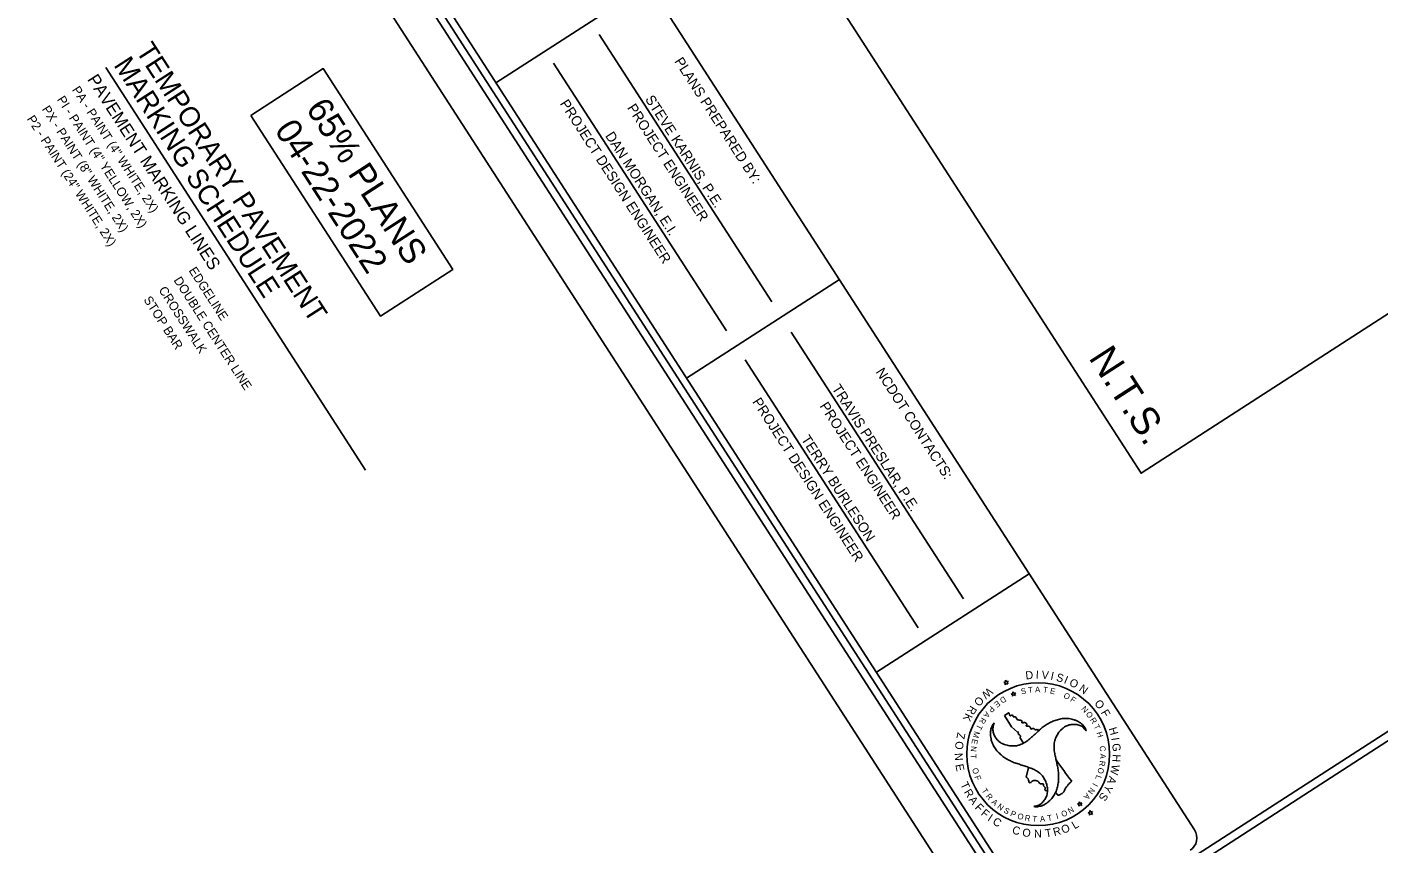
# Model space of a CAD drawing. Extents: x 2160312 to 2162215, y 789569 to 792090.
# Drawn here: x 2160312 to 2161255, y 790620 to 791189 of the extents above; entities that cross this region are included whole.
import ezdxf

# ---------------------------------------------------------------- set-up
doc = ezdxf.new("R2010")
doc.units = 0
for name, color, linetype in [('Default', 7, 'Continuous'), ('DEV BORDER CELL', 7, 'Continuous'), ('DEV TITLE SHEET CELL', 7, 'Continuous'), ('Gray Area Fill Shapes', 7, 'Continuous'), ('Old_Level_4', 7, 'Continuous'), ('Scratch_Level_4', 7, 'Continuous'), ('Sheet Plot Border Outside CELL', 7, 'Continuous'), ('Sheet Sticker Incomplete CELL', 7, 'Continuous')]:
    doc.layers.add(name, color=color, linetype=linetype)

msp = doc.modelspace()

# ---------------------------------------------------------------- linework, layer by layer
at = {"layer": 'DEV BORDER CELL'}
msp.add_line((2160547.96, 790880.49), (2160366.85, 791161.07), dxfattribs=at)
at = {"layer": 'DEV TITLE SHEET CELL'}
for p, q in [((2160611.25, 791427.06), (2161126.03, 790629.59)), ((2160490.55, 791361.48), (2161292.92, 790118.52)), ((2160497.63, 791360.29), (2161018.15, 790553.95)), ((2161019.55, 790560.85), (2160504.76, 791358.31)), ((2160745.54, 791219.17), (2160638.96, 791150.48)), ((2160710.9, 791184.09), (2160831.22, 790997.65)), ((2160679.13, 791164.22), (2160799.67, 790977.47)), ((2161888.56, 791103.58), (2161032.36, 790550.88)), ((2161891.61, 791098.86), (2161035.42, 790546.16)), ((2160844.75, 790976.71), (2160964.84, 790790.65)), ((2160812.73, 790957.28), (2160933.26, 790770.5)), ((2161010.85, 790808.18), (2160904.27, 790739.48)), ((2160994.16, 790732.73), (2160992.99, 790732.4)), ((2160992.99, 790732.4), (2160994.1, 790732)), ((2160994.1, 790732), (2160994.03, 790730.79)), ((2160994.1, 790732), (2160994.03, 790730.8)), ((2160994.03, 790730.79), (2160994.81, 790731.72)), ((2160994.03, 790730.8), (2160994.81, 790731.72)), ((2160994.23, 790733.94), (2160994.16, 790732.73)), ((2160994.88, 790732.93), (2160994.23, 790733.94)), ((2160994.81, 790731.72), (2160995.94, 790731.28)), ((2160994.81, 790731.72), (2160995.94, 790731.29)), ((2160996, 790733.23), (2160994.88, 790732.93)), ((2160995.29, 790732.29), (2160996, 790733.23)), ((2160995.94, 790731.29), (2160995.29, 790732.29)), ((2160999.36, 790724.64), (2160998.2, 790724.31)), ((2160998.2, 790724.31), (2160999.3, 790723.92)), ((2160999.3, 790723.92), (2160999.23, 790722.71)), ((2160999.23, 790722.71), (2161000.01, 790723.63)), ((2160999.43, 790725.85), (2160999.36, 790724.64)), ((2161000.08, 790724.84), (2160999.43, 790725.85)), ((2161000.01, 790723.63), (2161001.14, 790723.2)), ((2161001.21, 790725.15), (2161000.08, 790724.84)), ((2161000.49, 790724.21), (2161001.21, 790725.15)), ((2161001.14, 790723.2), (2161000.49, 790724.21)), ((2160993.65, 790709.4), (2160996.18, 790710.92)), ((2160998.41, 790701.4), (2160993.65, 790709.4)), ((2161002.61, 790697.78), (2160998.41, 790701.4)), ((2161004.31, 790693.99), (2161006.81, 790690.05)), ((2161010.35, 790673.16), (2161008.59, 790666.34)), ((2161045.58, 790647.96), (2161044.42, 790647.63)), ((2161044.42, 790647.63), (2161045.52, 790647.23)), ((2161045.52, 790647.23), (2161045.46, 790646.02)), ((2161045.46, 790646.02), (2161046.23, 790646.95)), ((2161045.65, 790649.16), (2161045.58, 790647.96)), ((2161046.3, 790648.15), (2161045.65, 790649.16)), ((2161046.23, 790646.95), (2161047.36, 790646.51)), ((2161047.43, 790648.46), (2161046.3, 790648.15)), ((2161046.71, 790647.52), (2161047.43, 790648.46)), ((2161047.36, 790646.51), (2161046.71, 790647.52)), ((2161053.02, 790641.84), (2161051.85, 790641.51)), ((2161053.08, 790643.05), (2161053.02, 790641.84)), ((2161053.74, 790642.04), (2161053.08, 790643.05)), ((2161054.86, 790642.34), (2161053.74, 790642.04)), ((2161054.15, 790641.4), (2161054.86, 790642.34)), ((2161051.85, 790641.51), (2161052.96, 790641.11)), ((2161052.96, 790641.11), (2161052.89, 790639.9)), ((2161052.89, 790639.9), (2161053.67, 790640.83)), ((2161053.67, 790640.83), (2161054.8, 790640.39)), ((2161054.8, 790640.39), (2161054.15, 790641.4))]:
    msp.add_line(p, q, dxfattribs=at)
msp.add_circle((2161017.03, 790682.35), 49.83, dxfattribs=at)
for centre, radius, start, end in [((2161243.56, 790823.19), 258.4, 208.52183, 208.81957), ((2161243.56, 790823.19), 258.4, 214.04685, 218.1669), ((2161117.38, 790624.01), 10.29, 302.84337, 32.84337)]:
    msp.add_arc(centre, radius, start, end, dxfattribs=at)
for points in [[(2160996.18, 790710.92), (2160996.36, 790711.15), (2160996.9, 790710.89), (2160997.17, 790709.43), (2160998.04, 790709.18), (2160998.53, 790709.53), (2160999.33, 790709.37), (2160999.68, 790708.48), (2161001.04, 790708.35), (2161001.65, 790707.81), (2161002.55, 790706.42), (2161005.27, 790705.83), (2161005.82, 790705.21), (2161005.49, 790704.74), (2161005.68, 790704.27), (2161007.53, 790704.42), (2161007.83, 790704.35), (2161009.17, 790703.43), (2161009.13, 790702.92), (2161008.59, 790702.42), (2161008.61, 790702.17), (2161009.17, 790701.94), (2161010.28, 790701.83), (2161011.51, 790701.14), (2161012.13, 790699.82), (2161013.27, 790700.26), (2161015.13, 790699.45), (2161015.9, 790699.53), (2161016.53, 790699.83)], [(2161013.94, 790645.94), (2161016.75, 790646.62), (2161019.26, 790648.06), (2161021.16, 790650.21), (2161022.73, 790652.88), (2161023.52, 790656.05), (2161023.55, 790658.41), (2161023.28, 790659.55), (2161022.96, 790661.46), (2161022.37, 790663.03), (2161020.89, 790665.82), (2161018.78, 790668.54), (2161015.89, 790670.67), (2161015.64, 790670.83), (2161012.67, 790672.31), (2161009.48, 790673.47), (2161006.37, 790674.55), (2161003.12, 790675.52), (2160999.89, 790676.59), (2160996.98, 790678.01), (2160993.75, 790679.89), (2160991.2, 790681.82), (2160988.77, 790684.21), (2160987.62, 790685.45), (2160986.88, 790686.71), (2160985.14, 790689.73), (2160984.16, 790693.1), (2160983.81, 790695.14), (2160983.81, 790696.94), (2160983.79, 790697.25), (2160984.34, 790700.51), (2160985.65, 790703.3), (2160986.35, 790704.14)], [(2160986.35, 790704.14), (2160985.52, 790701.31), (2160985.53, 790698.44), (2160986.43, 790695.73), (2160987.97, 790693.01), (2160990.33, 790690.74), (2160992.37, 790689.54), (2160993.45, 790689.18), (2160995.32, 790688.55), (2160996.91, 790688.27), (2161000.11, 790688.14), (2161003.49, 790688.61), (2161006.78, 790690.03), (2161007.05, 790690.17), (2161009.83, 790692), (2161012.42, 790694.2), (2161014.88, 790696.36), (2161017.38, 790698.68), (2161019.89, 790700.94), (2161022.58, 790702.75), (2161025.82, 790704.59), (2161028.78, 790705.86), (2161032.1, 790706.76), (2161033.7, 790707.13), (2161035.17, 790707.16), (2161038.69, 790707.13), (2161042.06, 790706.29), (2161044.02, 790705.57), (2161045.57, 790704.7), (2161045.84, 790704.56), (2161048.4, 790702.46), (2161050.18, 790699.92), (2161050.52, 790698.9)], [(2161050.64, 790698.88), (2161050.52, 790698.9), (2161048.52, 790701.01), (2161046, 790702.46), (2161043.21, 790703.04), (2161040.12, 790703.06), (2161036.96, 790702.15), (2161034.9, 790701), (2161034.06, 790700.21), (2161032.56, 790698.92), (2161031.5, 790697.71), (2161029.84, 790694.96), (2161028.53, 790691.83), (2161028.13, 790688.23), (2161028.11, 790687.94), (2161028.28, 790684.65), (2161028.91, 790681.26), (2161029.55, 790678.07), (2161030.31, 790674.77), (2161030.96, 790671.45), (2161031.21, 790668.21), (2161031.21, 790664.48), (2161030.82, 790661.3), (2161029.96, 790657.98), (2161029.46, 790656.38), (2161028.74, 790655.1), (2161026.98, 790652.05), (2161024.55, 790649.57), (2161022.95, 790648.21), (2161021.42, 790647.29), (2161021.17, 790647.13), (2161018.04, 790646), (2161014.95, 790645.74), (2161013.94, 790645.94)], [(2161004.31, 790693.99), (2161004.71, 790694.7), (2161004.48, 790695.45), (2161003.48, 790696.03), (2161003.09, 790696.67), (2161003.16, 790697.72), (2161002.61, 790697.78)], [(2161008.59, 790666.34), (2161010.08, 790665.07), (2161010.43, 790663.43), (2161010.73, 790662.73), (2161011.47, 790662.46), (2161013.34, 790663.89), (2161014.55, 790664.04), (2161017.5, 790662.93), (2161018.64, 790661.8), (2161020.48, 790661.61), (2161020.71, 790661.2), (2161020.75, 790660.37), (2161021.89, 790659.2), (2161021.71, 790657.56), (2161022.17, 790656.96), (2161023.49, 790657.1)], [(2161029.21, 790655.89), (2161030.98, 790653.77), (2161033.01, 790654.61), (2161034.55, 790655.57), (2161035.7, 790657.65), (2161038.02, 790661.16), (2161040.41, 790663.52)]]:
    msp.add_spline(points, degree=3, dxfattribs=at)
at = {"layer": 'Gray Area Fill Shapes'}
msp.add_line((2160878.45, 791013.22), (2160771.87, 790944.53), dxfattribs=at)
at = {"layer": 'Scratch_Level_4'}
msp.add_lwpolyline([(2161273.01, 791582.16), (2161539.58, 791169.21), (2161088.81, 790878.23), (2160822.24, 791291.18)], close=True, dxfattribs=at)
at = {"layer": 'Sheet Plot Border Outside CELL'}
msp.add_lwpolyline([(2160375.57, 791493.51), (2161291.05, 790075.32), (2162215.22, 790671.9), (2161299.74, 792090.09)], close=True, dxfattribs=at)
at = {"layer": 'Sheet Sticker Incomplete CELL'}
msp.add_lwpolyline([(2160468.04, 791127.78), (2160518.5, 791160.35), (2160608.84, 791020.4), (2160558.38, 790987.82)], close=True, dxfattribs=at)

# ---------------------------------------------------------------- texts
at = {"layer": 'Default'}
for s, height, p in [('PAVEMENT MARKING LINES', 8.75, (2160353.68, 791152.87)), ('PI - PAINT (4" YELLOW, 2X)', 6.25, (2160332.62, 791138.84)), ('PA - PAINT (4" WHITE, 2X)', 6.25, (2160343.12, 791145.62)), ('PX - PAINT (8" WHITE, 2X)', 6.25, (2160322.11, 791132.06)), ('P2 - PAINT (24" WHITE, 2X)', 6.25, (2160311.61, 791125.28)), ('EDGELINE', 6.25, (2160424.47, 791019.6)), ('DOUBLE CENTER LINE', 6.25, (2160413.97, 791012.82)), ('STOP BAR', 6.25, (2160392.96, 790999.26)), ('CROSSWALK', 6.25, (2160403.47, 791006.04))]:
    msp.add_text(s, height=height, rotation=302.84334, dxfattribs=at).set_placement(p)
at = {"layer": 'DEV BORDER CELL'}
for s, p in [('TEMPORARY PAVEMENT', (2160387.46, 791172.79)), ('MARKING SCHEDULE', (2160372.03, 791162.84))]:
    msp.add_text(s, height=13.9991, rotation=302.80314, dxfattribs=at).set_placement(p)
at = {"layer": 'DEV TITLE SHEET CELL'}
for s, height, rotation, p in [('PLANS PREPARED BY:', 7, 302.80314, (2160763.07, 791165.45)), ('STEVE KARNIS, P.E.', 7, 302.84334, (2160742.7, 791139.02)), ('PROJECT DESIGN ENGINEER', 7, 302.80314, (2160683.26, 791136)), ('PROJECT ENGINEER', 7, 302.80314, (2160730.17, 791133.03)), ('DAN MORGAN, E.I.', 7, 302.84334, (2160714.86, 791113.56)), ('NCDOT CONTACTS:', 7, 302.80314, (2160903.37, 790948.88)), ('TRAVIS PRESLAR, P.E.', 7, 302.84334, (2160872.88, 790937.36)), ('PROJECT DESIGN ENGINEER', 7, 302.80314, (2160817.47, 790928.1)), ('PROJECT ENGINEER', 7, 302.80314, (2160864.37, 790925.13)), ('TERRY BURLESON', 7, 302.84334, (2160851.42, 790902)), ('D', 5.58, 6.30238, (2161008.45, 790734.42)), ('I', 5.58, 358.71127, (2161015.32, 790735.09)), ('V', 5.58, 354.42394, (2161019.22, 790735.06)), ('I', 5.58, 347.71552, (2161025.29, 790734.44)), ('S', 5.58, 343.42818, (2161029.11, 790733.67)), ('I', 5.58, 337.22415, (2161034.52, 790732.06)), ('W', 5.58, 220.99332, (2160982.35, 790729.19)), ('S', 4.02, 12.803, (2161005.43, 790723.94)), ('T', 4.02, 7.72492, (2161010.24, 790724.95)), ('A', 4.02, 2.64683, (2161014.93, 790725.43)), ('T', 4.02, 352.49067, (2161020.18, 790725.44)), ('E', 4.02, 347.41258, (2161024.98, 790724.77)), ('O', 5.58, 332.93682, (2161038.14, 790730.61)), ('N', 5.58, 324.4294, (2161044.95, 790726.95)), ('O', 5.58, 229.95805, (2160975.47, 790723.21)), ('E', 4.02, 218.19343, (2160988.59, 790719.96)), ('D', 4.02, 213.11534, (2160993.04, 790723)), ('O', 4.02, 332.17833, (2161034.25, 790722.03)), ('F', 4.02, 327.10024, (2161038.97, 790719.52)), ('O', 5.58, 308.60829, (2161055.88, 790717.65)), ('K', 5.58, 244.63518, (2160966.48, 790711.35)), ('R', 5.58, 238.3974, (2160969.93, 790716.67)), ('R', 4.02, 238.50577, (2160977.64, 790708.31)), ('A', 4.02, 233.42768, (2160980.67, 790712.48)), ('P', 4.02, 228.3496, (2160984.1, 790716.27)), ('N', 4.02, 311.86599, (2161046.81, 790713.74)), ('O', 4.02, 306.7879, (2161049.97, 790710.31)), ('R', 4.02, 301.70982, (2161052.92, 790706.31)), ('F', 5.58, 300.10087, (2161060.58, 790711.51)), ('T', 4.02, 243.58385, (2160974.91, 790703.54)), ('T', 4.02, 296.63173, (2161055.49, 790701.87)), ('H', 5.58, 286.29732, (2161066.12, 790700.27)), ('O', 5.58, 265.36662, (2160959.48, 790691.58)), ('Z', 5.58, 259.01209, (2160960.86, 790697.89)), ('E', 4.02, 258.81811, (2160971.13, 790693.24)), ('M', 4.02, 253.74002, (2160972.67, 790698.65)), ('H', 4.02, 286.47557, (2161057.57, 790697.35)), ('I', 5.58, 278.64737, (2161067.98, 790693.57)), ('G', 5.58, 274.36004, (2161068.63, 790689.73)), ('N', 5.58, 273.80597, (2160958.75, 790683.03)), ('N', 4.02, 263.89619, (2160970.24, 790688.16)), ('T', 4.02, 274.05236, (2160969.77, 790682.26)), ('C', 4.02, 276.3194, (2161059.8, 790687.93)), ('A', 4.02, 266.16323, (2161060.28, 790682.83)), ('H', 5.58, 266.30657, (2161069.07, 790682.42)), ('E', 5.58, 281.795, (2160959.22, 790674.93)), ('O', 4.02, 284.20853, (2160970.97, 790672.2)), ('O', 4.02, 256.00706, (2161059.22, 790673.31)), ('R', 4.02, 261.08514, (2161060.01, 790678.05)), ('W', 5.58, 258.65662, (2161068.53, 790675.48)), ('T', 5.58, 295.53813, (2160962.64, 790661.41)), ('F', 4.02, 289.28661, (2160972.55, 790666.73)), ('I', 4.02, 240.7728, (2161055.37, 790662.56)), ('L', 4.02, 250.92897, (2161057.73, 790668.11)), ('A', 5.58, 249.61958, (2161066.71, 790667.47)), ('R', 5.58, 301.40898, (2160965.07, 790655.96)), ('A', 5.58, 307.64676, (2160968.25, 790650.47)), ('T', 4.02, 304.52087, (2160977.3, 790656.93)), ('R', 4.02, 309.59895, (2160980.22, 790652.89)), ('A', 4.02, 230.61663, (2161050.76, 790655.48)), ('N', 4.02, 235.69472, (2161053.58, 790659.4)), ('S', 5.58, 236.06824, (2161061.69, 790656.24)), ('Y', 5.58, 242.59171, (2161064.44, 790661.5)), ('F', 5.58, 314.6184, (2160972.48, 790644.78)), ('F', 5.58, 320.606, (2160976.64, 790640.34)), ('A', 4.02, 319.75512, (2160984.1, 790648.46)), ('N', 4.02, 324.83321, (2160988.14, 790645.04)), ('S', 4.02, 329.91129, (2160992.54, 790642.06)), ('P', 4.02, 334.98938, (2160997.17, 790639.6)), ('O', 4.02, 25.77022, (2161034.22, 790638.3)), ('N', 4.02, 30.5763, (2161039.13, 790640.64)), ('I', 5.58, 326.5936, (2160981.25, 790636.36)), ('C', 5.58, 330.84663, (2160984.75, 790633.83)), ('O', 4.02, 345.14555, (2161002.24, 790637.5)), ('R', 4.02, 350.22363, (2161007.4, 790636.18)), ('T', 4.02, 355.30172, (2161012.84, 790635.4)), ('A', 4.02, 5.45788, (2161018.47, 790635.13)), ('T', 4.02, 10.53597, (2161023.85, 790635.67)), ('I', 4.02, 15.61405, (2161030.07, 790637.05)), ('O', 5.58, 21.83298, (2161034.42, 790626.73)), ('L', 5.58, 30.27233, (2161042.39, 790629.89)), ('C', 5.58, 345.92405, (2160998.49, 790627.1)), ('O', 5.58, 353.29597, (2161005.73, 790625.18)), ('N', 5.58, 1.73532, (2161014.24, 790624.14)), ('T', 5.58, 9.72435, (2161022.36, 790624.32)), ('R', 5.58, 15.5952, (2161028.27, 790625.17))]:
    msp.add_text(s, height=height, rotation=rotation, dxfattribs=at).set_placement(p)
at = {"layer": 'Old_Level_4'}
msp.add_text('N.T.S.', height=19.647, rotation=302.84334, dxfattribs=at).set_placement((2161051.79, 790958.74))
at = {"layer": 'Sheet Sticker Incomplete CELL'}
for s, p in [('65% PLANS', (2160506, 791132.48)), ('04-22-2022', (2160484.07, 791117.58))]:
    msp.add_text(s, height=17.671, rotation=302.84334, dxfattribs=at).set_placement(p)

doc.saveas('drawing.dxf')
